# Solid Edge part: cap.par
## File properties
Author: Sarvanan
Template: Sync Iso Part.par
Last saved by: Sham
Revision: 15
Application: Solid Edge
Accuracy: 0.990
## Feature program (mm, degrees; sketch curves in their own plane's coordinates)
sketch for "Hole_11" plane through (65.305, 0, 51.617) normal (0.00061, 0, 1) x-axis (0, -1, 0)
hole "Hole_11" diameter 6 through  CounterBoreDepth = 16 mm; VBottomAngle = 118 deg
pattern "unnamed Pattern 1" of "Hole_11"
sketch for "unnamed Hole 1" plane through (100.5217, 1.5513, 39.9587) normal (0, 0, 1) x-axis (-1, 0, 0)
hole "unnamed Hole 1" through
sketch for "Hole_9" plane through (30.0931, 1.5513, 39.9587) normal (0, 0, 1) x-axis (1, 0, 0)
hole "Hole_9" diameter 12 through
pattern "unnamed Pattern 2" of "Hole_9", "unnamed Hole 1"
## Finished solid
Body 1: solid body, 23 faces, 56 edges, 32 vertices.
  Faces by surface: plane 12, cylinder 11
  Edges by curve: line 32, circle 12, ellipse 8, intersection 4
Bounding box of the edges (mm): 108.004 x 56.000 x 40.000, from (11.1731, -28, 11.617) to (119.1766, 28, 51.617).
Cylindrical faces by radius (mm): R3 x1, R4 x1, R6 x2, R17 x2, R24 x1, R48 x1, R54 x3
Planar faces by outward normal: +x 1, +y 1, +z 3, -x 2, -y 1, -z 4
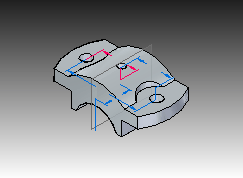
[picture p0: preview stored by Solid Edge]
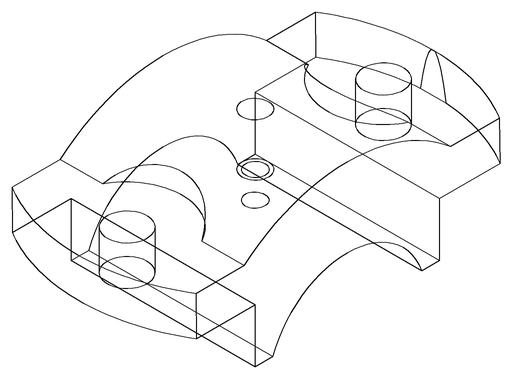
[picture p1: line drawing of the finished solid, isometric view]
